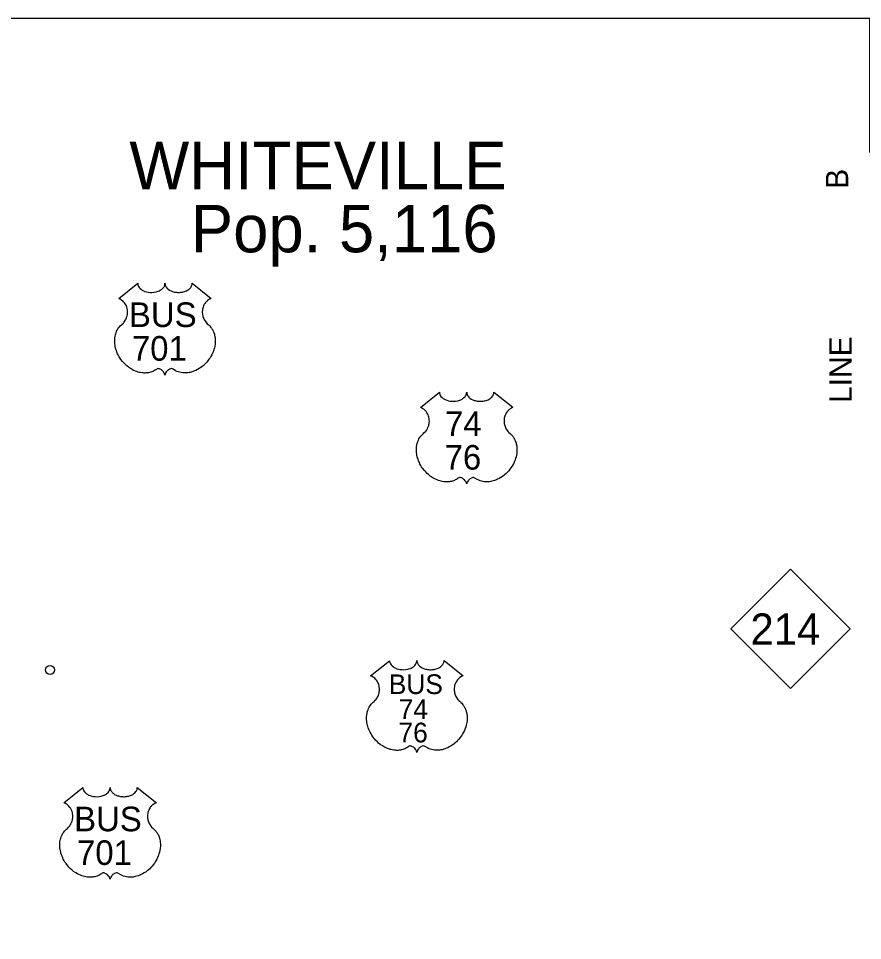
# Model space of a CAD drawing. Extents: x 5197761 to 5514561, y 1890130 to 2080942.
# Drawn here: x 5318095 to 5336955, y 2009899 to 2030497 of the extents above; entities that cross this region are included whole.
import ezdxf

# ---------------------------------------------------------------- set-up
doc = ezdxf.new("R2010")
doc.units = 0
for name, color, linetype in [('Exist Civil Demographics City Label', 7, 'Continuous'), ('Exist Road Primary NC Shield CELL', 7, 'Continuous'), ('Exist Road Primary NC Shield Number Label', 7, 'Continuous'), ('Exist Road Primary US Ramp 1 Lane  Attributed', 7, 'Continuous'), ('Exist Road Primary US Shield CELL', 7, 'Continuous'), ('Exist Road Primary US Shield Number Label', 7, 'Continuous'), ('Map Preparation County Match Line Label', 7, 'Continuous'), ('Map Preparation Inset Cut Line', 7, 'Continuous')]:
    doc.layers.add(name, color=color, linetype=linetype)

msp = doc.modelspace()

# ---------------------------------------------------------------- linework, layer by layer
at = {"layer": 'Exist Road Primary NC Shield CELL'}
msp.add_lwpolyline([(5334013, 2016864), (5335345, 2018196), (5336677, 2016864), (5335345, 2015532)], close=True, dxfattribs=at)
at = {"layer": 'Exist Road Primary US Ramp 1 Lane  Attributed'}
msp.add_line((5318800, 2015945), (5318800, 2015945), dxfattribs=at)
msp.add_circle((5318800, 2015945), 101, dxfattribs=at)
at = {"layer": 'Exist Road Primary US Shield CELL'}
for points in [[(5320760, 2024580), (5320761, 2024562), (5320766, 2024541), (5320769, 2024531), (5320779, 2024510), (5320795, 2024486), (5320817, 2024462), (5320843, 2024441), (5320860, 2024430), (5320889, 2024414), (5320922, 2024401), (5320958, 2024390), (5320996, 2024382), (5321036, 2024378), (5321077, 2024377), (5321121, 2024380), (5321169, 2024390), (5321191, 2024395), (5321216, 2024404), (5321239, 2024414), (5321264, 2024427), (5321285, 2024440), (5321301, 2024452), (5321323, 2024473), (5321341, 2024496), (5321349, 2024508), (5321355, 2024520), (5321364, 2024546), (5321367, 2024557), (5321369, 2024581), (5321370, 2024561), (5321372, 2024549), (5321375, 2024537), (5321380, 2024524), (5321389, 2024506), (5321399, 2024491), (5321418, 2024468), (5321430, 2024457), (5321441, 2024448), (5321470, 2024429), (5321504, 2024412), (5321520, 2024404), (5321537, 2024398), (5321559, 2024392), (5321581, 2024386), (5321603, 2024383), (5321626, 2024379), (5321649, 2024378), (5321668, 2024377), (5321691, 2024377), (5321712, 2024379), (5321734, 2024381), (5321758, 2024385), (5321778, 2024389), (5321803, 2024396), (5321826, 2024405), (5321847, 2024413), (5321873, 2024427), (5321894, 2024440), (5321910, 2024453), (5321928, 2024470), (5321946, 2024490), (5321956, 2024505), (5321964, 2024521), (5321970, 2024537), (5321974, 2024554), (5321977, 2024569), (5321977, 2024581), (5322402, 2024243), (5322392, 2024239), (5322369, 2024227), (5322351, 2024217), (5322321, 2024196), (5322309, 2024185), (5322296, 2024173), (5322285, 2024160), (5322275, 2024149), (5322262, 2024131), (5322251, 2024114), (5322240, 2024096), (5322232, 2024079), (5322219, 2024045), (5322213, 2024023), (5322209, 2024005), (5322204, 2023967), (5322203, 2023949), (5322203, 2023931), (5322204, 2023912), (5322206, 2023894), (5322209, 2023876), (5322212, 2023859), (5322217, 2023839), (5322225, 2023815), (5322234, 2023792), (5322253, 2023755), (5322278, 2023718), (5322296, 2023696), (5322314, 2023678), (5322340, 2023656), (5322354, 2023644), (5322371, 2023627), (5322397, 2023596), (5322408, 2023582), (5322419, 2023566), (5322429, 2023549), (5322439, 2023531), (5322447, 2023515), (5322462, 2023478), (5322473, 2023443), (5322478, 2023424), (5322486, 2023383), (5322489, 2023362), (5322492, 2023321), (5322492, 2023272), (5322488, 2023225), (5322480, 2023171), (5322472, 2023138), (5322461, 2023100), (5322450, 2023067), (5322431, 2023019), (5322414, 2022984), (5322391, 2022943), (5322376, 2022918), (5322358, 2022891), (5322336, 2022860), (5322310, 2022828), (5322278, 2022793), (5322253, 2022768), (5322220, 2022738), (5322200, 2022722), (5322171, 2022700), (5322132, 2022674), (5322093, 2022652), (5322060, 2022635), (5322031, 2022622), (5321994, 2022608), (5321931, 2022591), (5321908, 2022586), (5321881, 2022582), (5321856, 2022579), (5321831, 2022578), (5321798, 2022578), (5321765, 2022580), (5321734, 2022585), (5321701, 2022592), (5321668, 2022602), (5321637, 2022614), (5321606, 2022629), (5321553, 2022662), (5321538, 2022670), (5321529, 2022673), (5321509, 2022674), (5321490, 2022670), (5321470, 2022662), (5321459, 2022655), (5321443, 2022645), (5321431, 2022636), (5321416, 2022622), (5321406, 2022610), (5321399, 2022601), (5321384, 2022578), (5321378, 2022567), (5321373, 2022552), (5321368, 2022531), (5321361, 2022558), (5321354, 2022576), (5321345, 2022591), (5321335, 2022604), (5321320, 2022621), (5321307, 2022634), (5321291, 2022647), (5321274, 2022657), (5321260, 2022664), (5321248, 2022669), (5321232, 2022673), (5321220, 2022674), (5321209, 2022674), (5321195, 2022670), (5321176, 2022656), (5321158, 2022644), (5321138, 2022632), (5321114, 2022619), (5321097, 2022611), (5321077, 2022603), (5321052, 2022595), (5321026, 2022588), (5320999, 2022583), (5320976, 2022579), (5320951, 2022577), (5320928, 2022576), (5320904, 2022576), (5320881, 2022578), (5320856, 2022580), (5320823, 2022585), (5320797, 2022591), (5320769, 2022599), (5320740, 2022608), (5320709, 2022620), (5320670, 2022636), (5320643, 2022650), (5320601, 2022675), (5320551, 2022709), (5320514, 2022739), (5320486, 2022764), (5320446, 2022805), (5320422, 2022832), (5320385, 2022881), (5320361, 2022915), (5320346, 2022941), (5320323, 2022982), (5320311, 2023008), (5320294, 2023046), (5320282, 2023080), (5320271, 2023113), (5320266, 2023134), (5320258, 2023170), (5320253, 2023196), (5320248, 2023231), (5320245, 2023269), (5320245, 2023303), (5320246, 2023332), (5320249, 2023365), (5320255, 2023401), (5320261, 2023431), (5320268, 2023453), (5320277, 2023480), (5320288, 2023509), (5320303, 2023537), (5320316, 2023560), (5320333, 2023586), (5320349, 2023607), (5320371, 2023631), (5320394, 2023652), (5320414, 2023669), (5320439, 2023693), (5320452, 2023708), (5320467, 2023728), (5320480, 2023747), (5320489, 2023764), (5320502, 2023789), (5320510, 2023807), (5320520, 2023836), (5320525, 2023856), (5320530, 2023882), (5320533, 2023906), (5320534, 2023937), (5320534, 2023962), (5320530, 2023991), (5320525, 2024019), (5320518, 2024044), (5320508, 2024072), (5320498, 2024093), (5320482, 2024120), (5320463, 2024146), (5320445, 2024167), (5320426, 2024186), (5320408, 2024200), (5320391, 2024213), (5320369, 2024226), (5320348, 2024236), (5320335, 2024241)], [(5327502, 2022147), (5327503, 2022130), (5327507, 2022109), (5327510, 2022098), (5327520, 2022078), (5327536, 2022053), (5327559, 2022029), (5327584, 2022008), (5327601, 2021997), (5327630, 2021982), (5327663, 2021968), (5327700, 2021957), (5327737, 2021950), (5327778, 2021945), (5327818, 2021945), (5327862, 2021948), (5327910, 2021957), (5327933, 2021963), (5327957, 2021972), (5327981, 2021981), (5328006, 2021995), (5328026, 2022008), (5328042, 2022019), (5328065, 2022041), (5328083, 2022063), (5328090, 2022076), (5328097, 2022088), (5328106, 2022113), (5328108, 2022125), (5328110, 2022148), (5328111, 2022129), (5328114, 2022116), (5328117, 2022104), (5328122, 2022091), (5328131, 2022073), (5328141, 2022058), (5328160, 2022036), (5328172, 2022025), (5328182, 2022016), (5328211, 2021996), (5328245, 2021979), (5328262, 2021972), (5328279, 2021966), (5328300, 2021959), (5328323, 2021954), (5328345, 2021950), (5328367, 2021947), (5328390, 2021945), (5328409, 2021945), (5328432, 2021945), (5328454, 2021946), (5328476, 2021949), (5328500, 2021953), (5328519, 2021957), (5328545, 2021964), (5328568, 2021972), (5328588, 2021981), (5328614, 2021995), (5328636, 2022008), (5328651, 2022021), (5328670, 2022038), (5328687, 2022058), (5328698, 2022073), (5328705, 2022088), (5328712, 2022104), (5328716, 2022121), (5328718, 2022136), (5328718, 2022149), (5329143, 2021810), (5329133, 2021806), (5329110, 2021795), (5329092, 2021784), (5329063, 2021764), (5329050, 2021752), (5329038, 2021740), (5329026, 2021728), (5329016, 2021716), (5329004, 2021699), (5328993, 2021682), (5328982, 2021663), (5328974, 2021647), (5328961, 2021613), (5328955, 2021591), (5328951, 2021573), (5328946, 2021535), (5328944, 2021517), (5328944, 2021499), (5328945, 2021480), (5328947, 2021462), (5328950, 2021443), (5328953, 2021426), (5328959, 2021406), (5328966, 2021382), (5328975, 2021360), (5328995, 2021323), (5329020, 2021285), (5329038, 2021264), (5329055, 2021246), (5329081, 2021224), (5329096, 2021211), (5329112, 2021195), (5329139, 2021164), (5329149, 2021149), (5329160, 2021133), (5329170, 2021116), (5329180, 2021098), (5329188, 2021082), (5329203, 2021046), (5329214, 2021010), (5329219, 2020992), (5329227, 2020950), (5329230, 2020930), (5329234, 2020889), (5329234, 2020840), (5329230, 2020793), (5329221, 2020738), (5329214, 2020706), (5329203, 2020668), (5329192, 2020635), (5329172, 2020586), (5329155, 2020551), (5329133, 2020510), (5329118, 2020485), (5329100, 2020459), (5329077, 2020428), (5329051, 2020395), (5329020, 2020361), (5328994, 2020335), (5328961, 2020306), (5328941, 2020289), (5328913, 2020268), (5328873, 2020242), (5328835, 2020219), (5328802, 2020202), (5328773, 2020190), (5328735, 2020175), (5328672, 2020158), (5328650, 2020153), (5328622, 2020149), (5328597, 2020147), (5328572, 2020145), (5328539, 2020145), (5328506, 2020148), (5328475, 2020152), (5328443, 2020159), (5328409, 2020169), (5328378, 2020181), (5328347, 2020197), (5328295, 2020230), (5328279, 2020238), (5328271, 2020240), (5328250, 2020241), (5328231, 2020237), (5328212, 2020229), (5328200, 2020223), (5328184, 2020213), (5328172, 2020203), (5328158, 2020189), (5328148, 2020178), (5328140, 2020169), (5328125, 2020145), (5328120, 2020134), (5328114, 2020120), (5328110, 2020099), (5328103, 2020125), (5328095, 2020143), (5328086, 2020158), (5328077, 2020171), (5328062, 2020189), (5328048, 2020201), (5328032, 2020214), (5328015, 2020225), (5328002, 2020232), (5327989, 2020237), (5327974, 2020240), (5327961, 2020241), (5327951, 2020241), (5327937, 2020238), (5327918, 2020224), (5327899, 2020211), (5327880, 2020199), (5327856, 2020187), (5327839, 2020178), (5327818, 2020170), (5327794, 2020162), (5327768, 2020156), (5327741, 2020150), (5327717, 2020147), (5327692, 2020144), (5327669, 2020144), (5327645, 2020144), (5327623, 2020146), (5327597, 2020148), (5327565, 2020153), (5327538, 2020159), (5327510, 2020166), (5327481, 2020175), (5327450, 2020187), (5327412, 2020204), (5327385, 2020218), (5327342, 2020242), (5327293, 2020276), (5327255, 2020307), (5327228, 2020332), (5327187, 2020373), (5327164, 2020400), (5327126, 2020448), (5327102, 2020483), (5327087, 2020509), (5327064, 2020550), (5327052, 2020576), (5327036, 2020613), (5327023, 2020648), (5327013, 2020680), (5327007, 2020701), (5326999, 2020738), (5326994, 2020764), (5326989, 2020799), (5326987, 2020836), (5326986, 2020871), (5326987, 2020899), (5326990, 2020933), (5326996, 2020968), (5327003, 2020999), (5327009, 2021021), (5327018, 2021047), (5327030, 2021077), (5327044, 2021105), (5327057, 2021128), (5327074, 2021153), (5327091, 2021174), (5327113, 2021198), (5327135, 2021220), (5327156, 2021237), (5327180, 2021261), (5327193, 2021275), (5327209, 2021296), (5327221, 2021314), (5327231, 2021331), (5327244, 2021356), (5327251, 2021375), (5327261, 2021403), (5327266, 2021423), (5327271, 2021449), (5327274, 2021474), (5327276, 2021504), (5327275, 2021529), (5327272, 2021559), (5327266, 2021587), (5327260, 2021611), (5327249, 2021639), (5327239, 2021660), (5327223, 2021688), (5327205, 2021714), (5327186, 2021735), (5327167, 2021754), (5327149, 2021768), (5327132, 2021780), (5327111, 2021793), (5327090, 2021803), (5327077, 2021809)], [(5326388, 2016151), (5326389, 2016134), (5326394, 2016113), (5326397, 2016102), (5326407, 2016082), (5326423, 2016057), (5326445, 2016033), (5326471, 2016013), (5326488, 2016002), (5326517, 2015986), (5326550, 2015972), (5326586, 2015962), (5326624, 2015954), (5326665, 2015950), (5326705, 2015949), (5326749, 2015952), (5326797, 2015961), (5326819, 2015967), (5326844, 2015976), (5326867, 2015985), (5326893, 2015999), (5326913, 2016012), (5326929, 2016023), (5326951, 2016045), (5326969, 2016067), (5326977, 2016080), (5326983, 2016092), (5326992, 2016118), (5326995, 2016129), (5326997, 2016152), (5326998, 2016133), (5327000, 2016120), (5327003, 2016108), (5327008, 2016095), (5327017, 2016077), (5327028, 2016062), (5327046, 2016040), (5327058, 2016029), (5327069, 2016020), (5327098, 2016000), (5327132, 2015983), (5327148, 2015976), (5327165, 2015970), (5327187, 2015963), (5327209, 2015958), (5327231, 2015954), (5327254, 2015951), (5327277, 2015949), (5327296, 2015949), (5327319, 2015949), (5327340, 2015950), (5327362, 2015953), (5327386, 2015957), (5327406, 2015961), (5327431, 2015968), (5327454, 2015976), (5327475, 2015985), (5327501, 2015999), (5327522, 2016012), (5327538, 2016025), (5327557, 2016042), (5327574, 2016062), (5327584, 2016077), (5327592, 2016092), (5327598, 2016108), (5327603, 2016125), (5327605, 2016140), (5327605, 2016153), (5328030, 2015814), (5328020, 2015810), (5327997, 2015799), (5327979, 2015788), (5327949, 2015768), (5327937, 2015756), (5327924, 2015745), (5327913, 2015732), (5327903, 2015720), (5327890, 2015703), (5327879, 2015686), (5327868, 2015667), (5327861, 2015651), (5327848, 2015617), (5327841, 2015595), (5327837, 2015577), (5327832, 2015539), (5327831, 2015521), (5327831, 2015503), (5327832, 2015484), (5327834, 2015466), (5327837, 2015447), (5327840, 2015431), (5327845, 2015410), (5327853, 2015387), (5327862, 2015364), (5327882, 2015327), (5327907, 2015289), (5327924, 2015268), (5327942, 2015250), (5327968, 2015228), (5327982, 2015215), (5327999, 2015199), (5328025, 2015168), (5328036, 2015153), (5328047, 2015137), (5328057, 2015120), (5328067, 2015102), (5328075, 2015086), (5328090, 2015050), (5328101, 2015015), (5328106, 2014996), (5328114, 2014954), (5328117, 2014934), (5328120, 2014893), (5328120, 2014844), (5328117, 2014797), (5328108, 2014742), (5328100, 2014710), (5328089, 2014672), (5328078, 2014639), (5328059, 2014591), (5328042, 2014555), (5328019, 2014514), (5328004, 2014489), (5327986, 2014463), (5327964, 2014432), (5327938, 2014399), (5327907, 2014365), (5327881, 2014340), (5327848, 2014310), (5327828, 2014293), (5327799, 2014272), (5327760, 2014246), (5327721, 2014223), (5327689, 2014206), (5327659, 2014194), (5327622, 2014180), (5327559, 2014162), (5327536, 2014157), (5327509, 2014153), (5327484, 2014151), (5327459, 2014149), (5327426, 2014149), (5327393, 2014152), (5327362, 2014156), (5327330, 2014163), (5327296, 2014173), (5327265, 2014185), (5327234, 2014201), (5327181, 2014234), (5327166, 2014242), (5327157, 2014244), (5327137, 2014245), (5327118, 2014241), (5327098, 2014233), (5327087, 2014227), (5327071, 2014217), (5327059, 2014207), (5327044, 2014193), (5327034, 2014182), (5327027, 2014173), (5327012, 2014149), (5327007, 2014138), (5327001, 2014124), (5326996, 2014103), (5326990, 2014130), (5326982, 2014147), (5326973, 2014162), (5326963, 2014176), (5326948, 2014193), (5326935, 2014205), (5326919, 2014218), (5326902, 2014229), (5326888, 2014236), (5326876, 2014241), (5326860, 2014244), (5326848, 2014245), (5326838, 2014245), (5326823, 2014242), (5326804, 2014228), (5326786, 2014215), (5326766, 2014203), (5326743, 2014191), (5326725, 2014183), (5326705, 2014175), (5326681, 2014166), (5326654, 2014160), (5326628, 2014154), (5326604, 2014151), (5326579, 2014148), (5326556, 2014148), (5326532, 2014148), (5326510, 2014150), (5326484, 2014152), (5326452, 2014157), (5326425, 2014163), (5326397, 2014170), (5326368, 2014179), (5326337, 2014191), (5326298, 2014208), (5326272, 2014222), (5326229, 2014246), (5326179, 2014281), (5326142, 2014311), (5326114, 2014336), (5326074, 2014377), (5326050, 2014404), (5326013, 2014452), (5325989, 2014487), (5325974, 2014513), (5325951, 2014554), (5325939, 2014580), (5325923, 2014617), (5325910, 2014652), (5325899, 2014684), (5325894, 2014705), (5325886, 2014742), (5325881, 2014768), (5325876, 2014803), (5325873, 2014840), (5325873, 2014875), (5325874, 2014904), (5325877, 2014937), (5325883, 2014972), (5325889, 2015003), (5325896, 2015025), (5325905, 2015051), (5325917, 2015081), (5325931, 2015109), (5325944, 2015132), (5325961, 2015157), (5325977, 2015179), (5325999, 2015202), (5326022, 2015224), (5326043, 2015241), (5326067, 2015265), (5326080, 2015279), (5326095, 2015300), (5326108, 2015318), (5326117, 2015335), (5326130, 2015360), (5326138, 2015379), (5326148, 2015407), (5326153, 2015427), (5326158, 2015453), (5326161, 2015478), (5326162, 2015508), (5326162, 2015533), (5326158, 2015563), (5326153, 2015591), (5326146, 2015615), (5326136, 2015644), (5326126, 2015664), (5326110, 2015692), (5326092, 2015718), (5326073, 2015739), (5326054, 2015758), (5326036, 2015772), (5326019, 2015784), (5325997, 2015797), (5325976, 2015808), (5325963, 2015813)], [(5319534, 2013316), (5319535, 2013298), (5319540, 2013278), (5319543, 2013267), (5319553, 2013246), (5319569, 2013222), (5319591, 2013198), (5319617, 2013177), (5319634, 2013166), (5319663, 2013150), (5319696, 2013137), (5319732, 2013126), (5319770, 2013119), (5319811, 2013114), (5319851, 2013113), (5319895, 2013116), (5319943, 2013126), (5319965, 2013132), (5319990, 2013140), (5320013, 2013150), (5320039, 2013163), (5320059, 2013176), (5320075, 2013188), (5320097, 2013209), (5320115, 2013232), (5320123, 2013244), (5320129, 2013256), (5320138, 2013282), (5320141, 2013293), (5320143, 2013317), (5320144, 2013297), (5320146, 2013285), (5320149, 2013273), (5320154, 2013260), (5320164, 2013242), (5320174, 2013227), (5320193, 2013204), (5320204, 2013193), (5320215, 2013185), (5320244, 2013165), (5320278, 2013148), (5320294, 2013140), (5320311, 2013134), (5320333, 2013128), (5320355, 2013123), (5320377, 2013119), (5320400, 2013115), (5320423, 2013114), (5320442, 2013113), (5320465, 2013113), (5320486, 2013115), (5320508, 2013117), (5320532, 2013121), (5320552, 2013126), (5320577, 2013132), (5320600, 2013141), (5320621, 2013149), (5320647, 2013163), (5320668, 2013177), (5320684, 2013189), (5320703, 2013206), (5320720, 2013227), (5320730, 2013241), (5320738, 2013257), (5320744, 2013273), (5320749, 2013290), (5320751, 2013305), (5320751, 2013317), (5321176, 2012979), (5321166, 2012975), (5321143, 2012964), (5321125, 2012953), (5321095, 2012932), (5321083, 2012921), (5321070, 2012909), (5321059, 2012896), (5321049, 2012885), (5321036, 2012868), (5321025, 2012850), (5321014, 2012832), (5321007, 2012815), (5320994, 2012781), (5320987, 2012760), (5320983, 2012741), (5320978, 2012703), (5320977, 2012685), (5320977, 2012667), (5320978, 2012649), (5320980, 2012630), (5320983, 2012612), (5320986, 2012595), (5320991, 2012575), (5320999, 2012551), (5321008, 2012528), (5321028, 2012491), (5321053, 2012454), (5321070, 2012432), (5321088, 2012414), (5321114, 2012392), (5321128, 2012380), (5321145, 2012363), (5321171, 2012333), (5321182, 2012318), (5321193, 2012302), (5321203, 2012285), (5321213, 2012267), (5321221, 2012251), (5321236, 2012214), (5321247, 2012179), (5321252, 2012160), (5321260, 2012119), (5321263, 2012098), (5321266, 2012057), (5321266, 2012008), (5321263, 2011961), (5321254, 2011907), (5321246, 2011874), (5321235, 2011836), (5321225, 2011803), (5321205, 2011755), (5321188, 2011720), (5321166, 2011679), (5321150, 2011654), (5321132, 2011627), (5321110, 2011596), (5321084, 2011564), (5321053, 2011529), (5321027, 2011504), (5320994, 2011474), (5320974, 2011458), (5320945, 2011436), (5320906, 2011410), (5320867, 2011388), (5320835, 2011371), (5320805, 2011358), (5320768, 2011344), (5320705, 2011327), (5320682, 2011322), (5320655, 2011318), (5320630, 2011315), (5320605, 2011314), (5320572, 2011314), (5320539, 2011316), (5320508, 2011321), (5320476, 2011328), (5320442, 2011338), (5320411, 2011350), (5320380, 2011365), (5320327, 2011398), (5320312, 2011406), (5320303, 2011409), (5320283, 2011410), (5320264, 2011406), (5320244, 2011398), (5320233, 2011392), (5320217, 2011381), (5320205, 2011372), (5320190, 2011358), (5320180, 2011346), (5320173, 2011337), (5320158, 2011314), (5320153, 2011303), (5320147, 2011289), (5320142, 2011267), (5320136, 2011294), (5320128, 2011312), (5320119, 2011327), (5320109, 2011340), (5320094, 2011357), (5320081, 2011370), (5320065, 2011383), (5320048, 2011393), (5320034, 2011400), (5320022, 2011405), (5320006, 2011409), (5319994, 2011410), (5319984, 2011410), (5319969, 2011406), (5319950, 2011393), (5319932, 2011380), (5319912, 2011368), (5319889, 2011355), (5319871, 2011347), (5319851, 2011339), (5319827, 2011331), (5319800, 2011324), (5319774, 2011319), (5319750, 2011315), (5319725, 2011313), (5319702, 2011312), (5319678, 2011312), (5319656, 2011314), (5319630, 2011316), (5319598, 2011321), (5319571, 2011327), (5319543, 2011335), (5319514, 2011344), (5319483, 2011356), (5319444, 2011372), (5319418, 2011386), (5319375, 2011411), (5319325, 2011445), (5319288, 2011475), (5319260, 2011500), (5319220, 2011541), (5319196, 2011568), (5319159, 2011617), (5319135, 2011652), (5319120, 2011677), (5319097, 2011718), (5319085, 2011744), (5319069, 2011782), (5319056, 2011816), (5319045, 2011849), (5319040, 2011870), (5319032, 2011906), (5319027, 2011932), (5319022, 2011968), (5319019, 2012005), (5319019, 2012039), (5319020, 2012068), (5319023, 2012101), (5319029, 2012137), (5319035, 2012167), (5319042, 2012189), (5319051, 2012216), (5319063, 2012245), (5319077, 2012273), (5319090, 2012297), (5319107, 2012322), (5319123, 2012343), (5319145, 2012367), (5319168, 2012388), (5319189, 2012405), (5319213, 2012429), (5319226, 2012444), (5319241, 2012464), (5319254, 2012483), (5319263, 2012500), (5319276, 2012525), (5319284, 2012543), (5319294, 2012572), (5319299, 2012592), (5319304, 2012618), (5319307, 2012642), (5319308, 2012673), (5319308, 2012698), (5319304, 2012727), (5319299, 2012755), (5319292, 2012780), (5319282, 2012808), (5319272, 2012829), (5319256, 2012856), (5319238, 2012882), (5319219, 2012903), (5319200, 2012922), (5319182, 2012936), (5319165, 2012949), (5319143, 2012962), (5319122, 2012972), (5319109, 2012977)]]:
    msp.add_lwpolyline(points, close=True, dxfattribs=at)
at = {"layer": 'Map Preparation Inset Cut Line'}
msp.add_lwpolyline([(5337121, 2027499), (5337121, 2030497), (5298905, 2030497), (5298905, 1990962), (5337121, 1990962), (5337121, 1992535)], dxfattribs=at)

# ---------------------------------------------------------------- texts
at = {"layer": 'Exist Civil Demographics City Label'}
for s, p in [('WHITEVILLE', (5320573, 2026682)), ('Pop. 5,116', (5321946, 2025273))]:
    msp.add_text(s, height=1060, dxfattribs=at).set_placement(p)
at = {"layer": 'Exist Road Primary NC Shield Number Label'}
msp.add_text('214', height=700, dxfattribs=at).set_placement((5334450, 2016506))
at = {"layer": 'Exist Road Primary US Shield Number Label'}
for s, height, p in [('BUS', 550, (5320564, 2023604)), ('701', 550, (5320629, 2022852)), ('74', 550, (5327625, 2021171)), ('76', 550, (5327617, 2020419)), ('BUS', 440, (5326369, 2015405)), ('74', 440, (5326591, 2014848)), ('76', 440, (5326586, 2014326)), ('BUS', 550, (5319338, 2012340)), ('701', 550, (5319403, 2011588))]:
    msp.add_text(s, height=height, dxfattribs=at).set_placement(p)
at = {"layer": 'Map Preparation County Match Line Label'}
for s, p in [('B', (5336635, 2026691)), ('LINE', (5336712, 2021908))]:
    msp.add_text(s, height=500, rotation=90, dxfattribs=at).set_placement(p)

doc.saveas('drawing.dxf')
